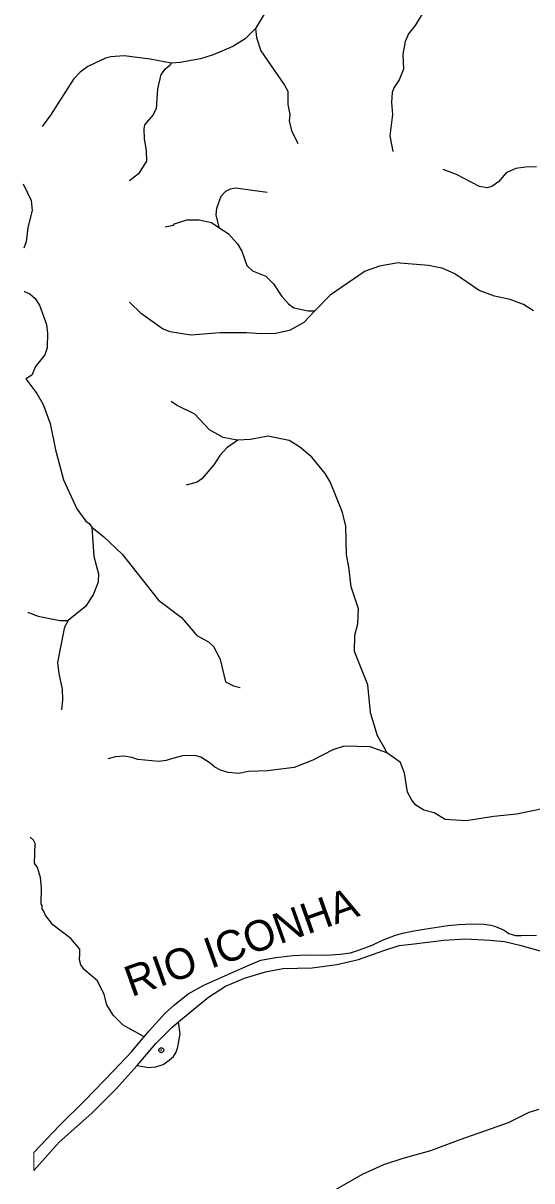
# Model space of a CAD drawing. Extents: x 317.8 to 344.1, y 7676.8 to 7704.8.
# Drawn here: x 317.874 to 319.533, y 7693.947 to 7697.725 of the extents above; entities that cross this region are included whole.
import ezdxf
from ezdxf.enums import TextEntityAlignment as Align

# ---------------------------------------------------------------- set-up
doc = ezdxf.new("R2010")
doc.units = 0
doc.header["$LTSCALE"] = 0.032
doc.header["$PDMODE"] = 32
doc.header["$PDSIZE"] = 0.016
doc.linetypes.add('SHORT_DASHED', pattern=[2.7, 1.5, -1.2])
for name, color, linetype, lineweight in [('2', 7, 'Continuous', 25), ('62', 7, 'SHORT_DASHED', 13), ('7', 7, 'Continuous', 25)]:
    doc.layers.add(name, color=color, linetype=linetype, lineweight=lineweight)
doc.layers.add('54', color=7, linetype='Continuous')
doc.layers.add('61', color=7, linetype='Continuous')

msp = doc.modelspace()

# ---------------------------------------------------------------- linework, layer by layer
at = {"layer": '2'}
for points in [[(318.2681, 7694.4168), (318.2848, 7694.4368), (318.3356, 7694.4932), (318.3676, 7694.5219), (318.4118, 7694.5572), (318.4637, 7694.5859), (318.5709, 7694.6334), (318.6173, 7694.6544), (318.6493, 7694.6677), (318.6979, 7694.6765), (318.7531, 7694.6831), (318.8006, 7694.6853), (318.8636, 7694.6842), (318.9077, 7694.6864), (318.942, 7694.6909), (318.9707, 7694.7008), (319.0127, 7694.7163), (319.0458, 7694.7328), (319.0889, 7694.7494), (319.111, 7694.756), (319.143, 7694.7615), (319.1883, 7694.7693), (319.259, 7694.7803), (319.2954, 7694.7836), (319.3385, 7694.7858), (319.3771, 7694.7847), (319.3992, 7694.7814), (319.4147, 7694.777), (319.4434, 7694.7649), (319.4578, 7694.7549), (319.4799, 7694.7483), (319.4986, 7694.7483), (319.5196, 7694.7494), (319.5483, 7694.7483)], [(318.3805, 7694.4661), (318.4191, 7694.4981), (318.4781, 7694.5467), (318.5341, 7694.5821), (318.596, 7694.6087), (318.6639, 7694.6293), (318.7214, 7694.6397), (318.8172, 7694.6426), (318.8969, 7694.6529), (318.9677, 7694.6691), (319.0502, 7694.6986), (319.1004, 7694.7149), (319.149, 7694.7208), (319.2464, 7694.7326), (319.3172, 7694.737), (319.3968, 7694.7326), (319.444, 7694.7281), (319.4941, 7694.7163), (319.5679, 7694.6957)], [(318.2458, 7694.3234), (318.307, 7694.3949), (318.3586, 7694.4479), (318.3805, 7694.4661)], [(317.9081, 7694.0402), (317.9921, 7694.1276), (318.075, 7694.2093), (318.1688, 7694.3065), (318.2285, 7694.3695), (318.2653, 7694.4135), (318.2681, 7694.4168)], [(317.9087, 7693.9815), (317.9914, 7694.0734), (318.0976, 7694.1678), (318.1772, 7694.2474), (318.2362, 7694.3123), (318.2458, 7694.3234)], [(318.8175, 7693.8755), (318.9807, 7693.9687), (319.0506, 7694.0008), (319.1132, 7694.0212), (319.2036, 7694.0459), (319.2997, 7694.0824), (319.4571, 7694.1377), (319.5241, 7694.1713), (319.5576, 7694.1815)]]:
    msp.add_lwpolyline(points, dxfattribs=at)
at = {"layer": '54'}
msp.add_point((318.3245, 7694.3735), dxfattribs=at)
at = {"layer": '62'}
msp.add_line((317.9081, 7694.0402), (317.9087, 7693.9815), dxfattribs=at)
at = {"layer": '7'}
for points in [[(319.4162, 7698.2532), (319.367, 7698.1766), (319.3063, 7698.0473), (319.3042, 7698.044), (319.2858, 7698.0161), (319.2659, 7697.9953), (319.2425, 7697.9634), (319.2247, 7697.9215), (319.2113, 7697.8946), (319.1909, 7697.8538), (319.1892, 7697.8116), (319.174, 7697.7532), (319.1527, 7697.717), (319.131, 7697.69), (319.1202, 7697.6652), (319.1125, 7697.6242), (319.1141, 7697.5746), (319.1008, 7697.54), (319.0829, 7697.5143), (319.0776, 7697.4986), (319.0759, 7697.4662), (319.0783, 7697.427), (319.0702, 7697.357), (319.0801, 7697.3068)], [(318.6943, 7697.8109), (318.6316, 7697.7081)], [(318.6316, 7697.7081), (318.5986, 7697.6745), (318.5577, 7697.6495), (318.4937, 7697.6217), (318.4528, 7697.6091), (318.3865, 7697.5965), (318.3572, 7697.5945)], [(318.6316, 7697.7081), (318.6349, 7697.6779), (318.6488, 7697.6352), (318.7266, 7697.5233), (318.7375, 7697.5031), (318.7377, 7697.4597), (318.7433, 7697.4269), (318.7419, 7697.4067), (318.7489, 7697.375), (318.7704, 7697.3329)], [(318.3572, 7697.5945), (318.2885, 7697.6073), (318.2037, 7697.618), (318.1597, 7697.6148), (318.1428, 7697.6107), (318.0843, 7697.5832), (318.0603, 7697.565), (318.038, 7697.5427), (317.9628, 7697.4252), (317.9358, 7697.3883)], [(318.3572, 7697.5945), (318.3527, 7697.5872), (318.3334, 7697.5722), (318.3232, 7697.5575), (318.3123, 7697.5104), (318.3072, 7697.4458), (318.2964, 7697.4247), (318.27, 7697.3938), (318.2674, 7697.3803), (318.2683, 7697.3476), (318.2747, 7697.3092), (318.276, 7697.2743), (318.2496, 7697.2335), (318.2202, 7697.2106)], [(319.5485, 7697.2561), (319.513, 7697.2553), (319.4811, 7697.2504), (319.4491, 7697.2364), (319.4243, 7697.2069), (319.4025, 7697.1921), (319.3879, 7697.1877), (319.3626, 7697.1921), (319.3622, 7697.1922), (319.2873, 7697.2308), (319.2439, 7697.2481)], [(317.8738, 7697.2007), (317.8997, 7697.1465), (317.9031, 7697.1133), (317.8894, 7697.0588), (317.8837, 7697.0115), (317.876, 7696.9914)], [(318.6702, 7697.1727), (318.5663, 7697.1862), (318.5492, 7697.183), (318.5334, 7697.1757), (318.5185, 7697.16), (318.5046, 7697.1206), (318.5022, 7697.0993), (318.5121, 7697.0585)], [(318.3372, 7697.0604), (318.3648, 7697.0664), (318.368, 7697.07), (318.4081, 7697.0833), (318.4479, 7697.0834), (318.488, 7697.0745), (318.5121, 7697.0585)], [(318.5121, 7697.0585), (318.5421, 7697.0385), (318.5736, 7697.0049), (318.5877, 7696.9815), (318.6039, 7696.9347), (318.622, 7696.9164), (318.666, 7696.8999), (318.6902, 7696.8742), (318.7156, 7696.8368), (318.7192, 7696.8316), (318.7397, 7696.8088), (318.7568, 7696.7966), (318.8038, 7696.786), (318.8259, 7696.786)], [(319.5383, 7696.7864), (319.506, 7696.8068), (319.4624, 7696.8236), (319.412, 7696.8346), (319.3617, 7696.8522), (319.2826, 7696.9069), (319.2408, 7696.9257), (319.2273, 7696.9283), (319.1967, 7696.9343), (319.1041, 7696.942), (319.0975, 7696.9425), (319.0367, 7696.932), (318.9891, 7696.9156), (318.8753, 7696.8378), (318.8259, 7696.786)], [(317.8776, 7696.8498), (317.8779, 7696.8496), (317.8952, 7696.8416), (317.913, 7696.8265), (317.9268, 7696.8052), (317.9499, 7696.7422), (317.9537, 7696.7132), (317.952, 7696.6653), (317.9441, 7696.6432), (317.9137, 7696.6047), (317.9023, 7696.576), (317.8824, 7696.5647), (317.9182, 7696.5164), (317.9392, 7696.4804), (317.9618, 7696.4189), (317.979, 7696.3325), (318.0058, 7696.235), (318.0492, 7696.14), (318.0778, 7696.1003), (318.089, 7696.0921), (318.0973, 7696.0803)], [(318.8259, 7696.786), (318.79, 7696.7483), (318.7429, 7696.7225), (318.6972, 7696.7126), (318.6503, 7696.711), (318.602, 7696.7147), (318.5972, 7696.7151), (318.5163, 7696.7151), (318.4204, 7696.7069), (318.3533, 7696.7177), (318.3286, 7696.7272), (318.26, 7696.7762), (318.2202, 7696.8145)], [(318.5745, 7696.3645), (318.5715, 7696.3644), (318.5264, 7696.3726), (318.4821, 7696.3985), (318.4338, 7696.4487), (318.3745, 7696.4785), (318.3571, 7696.4902)], [(318.5745, 7696.3645), (318.5744, 7696.3645), (318.5383, 7696.3388), (318.5153, 7696.3148), (318.496, 7696.2841), (318.4566, 7696.2381), (318.441, 7696.2269), (318.406, 7696.2171)], [(319.0599, 7695.3441), (319.055, 7695.3564), (319.0298, 7695.3999), (319.0076, 7695.4717), (319.0071, 7695.4768), (318.9982, 7695.5657), (318.955, 7695.6751), (318.9562, 7695.728), (318.9657, 7695.7652), (318.9675, 7695.8144), (318.944, 7695.8856), (318.9364, 7695.9504), (318.9284, 7695.9902), (318.9267, 7696.0847), (318.914, 7696.1317), (318.8749, 7696.2279), (318.8593, 7696.2558), (318.8157, 7696.3086), (318.7758, 7696.3429), (318.7412, 7696.3628), (318.6715, 7696.3776), (318.615, 7696.3664), (318.5745, 7696.3645)], [(318.0973, 7696.0803), (318.1044, 7695.9843), (318.12, 7695.9279), (318.1181, 7695.9005), (318.1023, 7695.8599), (318.0769, 7695.822), (318.0209, 7695.7759)], [(318.0973, 7696.0803), (318.1373, 7696.0489), (318.1965, 7695.9921), (318.3158, 7695.8427), (318.3906, 7695.7857), (318.44, 7695.7267), (318.4786, 7695.7058), (318.4943, 7695.6911), (318.5159, 7695.6517), (318.5168, 7695.6481), (318.5343, 7695.5755), (318.5597, 7695.5627), (318.5821, 7695.557)], [(317.8889, 7695.8022), (317.891, 7695.8015), (317.9227, 7695.7903), (317.9939, 7695.7757), (318.0209, 7695.7759)], [(318.0209, 7695.7759), (318.0082, 7695.7538), (318.0064, 7695.7444), (317.9863, 7695.6384), (317.99, 7695.6024), (318.001, 7695.5517), (318.0025, 7695.5164), (317.9985, 7695.4844)], [(319.0599, 7695.3441), (319.006, 7695.363), (318.9209, 7695.3654), (318.8842, 7695.3534), (318.8189, 7695.3204), (318.7583, 7695.2963), (318.6708, 7695.2855), (318.6089, 7695.283), (318.5774, 7695.2766), (318.5422, 7695.28), (318.5173, 7695.2873), (318.4991, 7695.2968), (318.4841, 7695.3106), (318.453, 7695.33), (318.4342, 7695.3353), (318.3937, 7695.3343), (318.3496, 7695.3217), (318.3402, 7695.319), (318.3166, 7695.3157), (318.2474, 7695.3221), (318.2281, 7695.3289), (318.2037, 7695.3327), (318.1746, 7695.331), (318.1501, 7695.3247)], [(319.6269, 7695.1729), (319.483, 7695.1434), (319.4096, 7695.1364), (319.3192, 7695.1218), (319.2502, 7695.1267), (319.2143, 7695.1484), (319.1811, 7695.1565), (319.1547, 7695.1734), (319.1416, 7695.1895), (319.1278, 7695.2153), (319.1175, 7695.2779), (319.1047, 7695.3126), (319.0743, 7695.334), (319.0599, 7695.3441)], [(318.2681, 7694.4168), (318.2, 7694.4556), (318.1678, 7694.4879), (318.147, 7694.5215), (318.1382, 7694.5555), (318.1166, 7694.6), (318.0749, 7694.6344), (318.0729, 7694.6372), (318.0622, 7694.6519), (318.058, 7694.6682), (318.0583, 7694.689), (318.0585, 7694.7029), (318.0289, 7694.7384), (317.9702, 7694.7832), (317.9454, 7694.8155), (317.9415, 7694.8278), (317.9358, 7694.8344), (317.9357, 7694.8459), (317.9325, 7694.8514), (317.934, 7694.9036), (317.9308, 7694.9372), (317.9205, 7694.9693), (317.9113, 7694.9835), (317.9128, 7695.0484), (317.907, 7695.059), (317.8969, 7695.0683)], [(318.2458, 7694.3234), (318.2838, 7694.3168), (318.3063, 7694.3194), (318.3302, 7694.3273), (318.3501, 7694.3406), (318.3646, 7694.3525), (318.3726, 7694.3671), (318.3779, 7694.3843), (318.3858, 7694.4267), (318.3805, 7694.4661)]]:
    msp.add_lwpolyline(points, dxfattribs=at)

# ---------------------------------------------------------------- texts
at = {"layer": '61'}
msp.add_text('RIO ICONHA', height=0.1, rotation=19.596, dxfattribs=at).set_placement((318.6016, 7694.6799), align=Align.CENTER)

doc.saveas('drawing.dxf')
